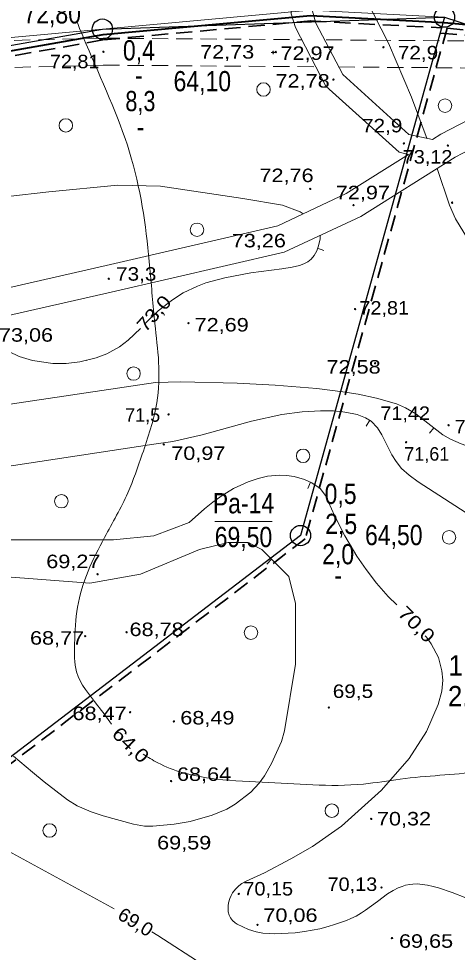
# Model space of a CAD drawing. Extents: x 628176 to 629009, y 6439913 to 6440496.
# Drawn here: x 628531.9 to 628597, y 6440288.3 to 6440426.6 of the extents above; entities that cross this region are included whole.
import ezdxf
from ezdxf.enums import TextEntityAlignment as Align

# ---------------------------------------------------------------- set-up
doc = ezdxf.new("R2010")
doc.units = 0
doc.header["$LTSCALE"] = 0.8
doc.linetypes.add('MEDIUM_DASHED', pattern=[4.5, 3, -1.5])
for name, color, linetype, lineweight in [('1', 7, 'Continuous', 13), ('11', 7, 'Continuous', 13), ('12', 7, 'Continuous', 13), ('14', 7, 'Continuous', 25), ('16', 7, 'Continuous', 13), ('21', 7, 'MEDIUM_DASHED', 35), ('3', 7, 'Continuous', 13)]:
    doc.layers.add(name, color=color, linetype=linetype, lineweight=lineweight)

msp = doc.modelspace()

# ---------------------------------------------------------------- hatches: boundary and pattern name
at = {"layer": '1'}
for points in [[(628544.6156, 6440421.7562, 1), (628544.4156, 6440421.7562, 1)], [(628569.7739, 6440421.6419, 1), (628569.5739, 6440421.6419, 1)], [(628570.1672, 6440421.7093, 1), (628569.9672, 6440421.7093, 1)], [(628586.1488, 6440422.4212, 1), (628585.9488, 6440422.4212, 1)], [(628578.7353, 6440417.613, 1), (628578.5353, 6440417.613, 1)], [(628589.1774, 6440408.173, 1), (628588.9774, 6440408.173, 1)], [(628595.7088, 6440407.8353, 1), (628595.5088, 6440407.8353, 1)], [(628575.2928, 6440401.4134, 1), (628575.0928, 6440401.4134, 1)], [(628596.329, 6440399.3821, 1), (628596.129, 6440399.3821, 1)], [(628581.7064, 6440399.0352, 1), (628581.5064, 6440399.0352, 1)], [(628570.9599, 6440394.0094, 1), (628570.7599, 6440394.0094, 1)], [(628545.4093, 6440388.101, 1), (628545.2093, 6440388.101, 1)], [(628581.9348, 6440383.6154, 1), (628581.7348, 6440383.6154, 1)], [(628557.2245, 6440381.5249, 1), (628557.0245, 6440381.5249, 1)], [(628584.9118, 6440375.5862, 1), (628584.7118, 6440375.5862, 1)], [(628554.2758, 6440368.0094, 1), (628554.0758, 6440368.0094, 1)], [(628595.8117, 6440366.4053, 1), (628595.6117, 6440366.4053, 1)], [(628553.5654, 6440363.5639, 1), (628553.3654, 6440363.5639, 1)], [(628589.5007, 6440363.8819, 1), (628589.3007, 6440363.8819, 1)], [(628543.7614, 6440344.3181, 1), (628543.5614, 6440344.3181, 1)], [(628548.0623, 6440335.7123, 1), (628547.8623, 6440335.7123, 1)], [(628541.9325, 6440335.1404, 1), (628541.7325, 6440335.1404, 1)], [(628578.0506, 6440324.5525, 1), (628577.8506, 6440324.5525, 1)], [(628548.5758, 6440323.8709, 1), (628548.3758, 6440323.8709, 1)], [(628555.0651, 6440322.5003, 1), (628554.8651, 6440322.5003, 1)], [(628554.6487, 6440313.6713, 1), (628554.4487, 6440313.6713, 1)], [(628584.3303, 6440308.048, 1), (628584.1303, 6440308.048, 1)], [(628560.1473, 6440304.6241, 1), (628559.9473, 6440304.6241, 1)], [(628564.6969, 6440296.9314, 1), (628564.4969, 6440296.9314, 1)], [(628585.8622, 6440297.8938, 1), (628585.6622, 6440297.8938, 1)], [(628567.4708, 6440292.3538, 1), (628567.2708, 6440292.3538, 1)], [(628587.4153, 6440290.3952, 1), (628587.2153, 6440290.3952, 1)]]:
    msp.add_hatch(color=256, dxfattribs=at).paths.add_polyline_path(points)

# ---------------------------------------------------------------- linework, layer by layer
for p, q in [((628576.01, 6440426), (628580, 6440418.38)), ((628573, 6440425.35), (628577.48, 6440416.66)), ((628569.67, 6440421.64), (628569.42, 6440421.64)), ((628569.67, 6440421.64), (628569.67, 6440421.89)), ((628569.67, 6440421.64), (628569.67, 6440421.39)), ((628569.67, 6440421.64), (628569.92, 6440421.64)), ((628580, 6440418.38), (628589.79, 6440409.49)), ((628577.48, 6440416.66), (628588.36, 6440406.85)), ((628605.41, 6440415.18), (628594.58, 6440409.55)), ((628607.25, 6440411.62), (628596.67, 6440406.14)), ((628589.79, 6440409.49), (628593.3, 6440408.74)), ((628594.58, 6440409.55), (628593.3, 6440408.74)), ((628589.76, 6440406.52), (628580.53, 6440400.72)), ((628588.36, 6440406.85), (628589.76, 6440406.52)), ((628596.67, 6440406.14), (628582.68, 6440397.35)), ((628580.53, 6440400.72), (628570.38, 6440395.95)), ((628582.68, 6440397.35), (628571.34, 6440392.07)), ((628570.38, 6440395.95), (628544.93, 6440390.06)), ((628571.34, 6440392.07), (628545.69, 6440386.14)), ((628544.93, 6440390.06), (628489.7, 6440377.44)), ((628545.69, 6440386.14), (628490.46, 6440373.52))]:
    msp.add_line(p, q, dxfattribs=at)
at = {"layer": '1', "linetype": 'MEDIUM_DASHED'}
for p, q in [((628544.47, 6440423.76), (628531.15, 6440423.43)), ((628544.53, 6440423.76), (628573.94, 6440423.53)), ((628577.55, 6440423.51), (628605.07, 6440423.3)), ((628544.56, 6440419.76), (628531.24, 6440419.43)), ((628544.5, 6440419.76), (628576.01, 6440419.52)), ((628579.42, 6440419.49), (628605.04, 6440419.3))]:
    msp.add_line(p, q, dxfattribs=at)
at = {"layer": '1'}
for points in [[(628576.01, 6440426), (628575.38, 6440428.31), (628576, 6440430.63), (628579.19, 6440436.17), (628580.37, 6440438.23)], [(628572.35, 6440429), (628572.35, 6440427.37), (628573, 6440425.35)]]:
    msp.add_lwpolyline(points, dxfattribs=at)
for centre, radius in [((628544.5156, 6440421.7562), 0.1), ((628569.6739, 6440421.6419), 0.1), ((628570.0672, 6440421.7093), 0.1), ((628586.0488, 6440422.4212), 0.1), ((628578.6353, 6440417.613), 0.1), ((628568.2597, 6440416.1603), 1), ((628595.1825, 6440413.7612), 1), ((628538.9379, 6440410.829), 1), ((628589.0774, 6440408.173), 0.1), ((628595.6088, 6440407.8353), 0.1), ((628575.1928, 6440401.4134), 0.1), ((628596.229, 6440399.3821), 0.1), ((628581.6064, 6440399.0352), 0.1), ((628558.3969, 6440395.3684), 1), ((628570.8599, 6440394.0094), 0.1), ((628545.3093, 6440388.101), 0.1), ((628581.8348, 6440383.6154), 0.1), ((628557.1245, 6440381.5249), 0.1), ((628548.9908, 6440374.0544), 1), ((628584.8118, 6440375.5862), 0.1), ((628554.1758, 6440368.0094), 0.1), ((628595.7117, 6440366.4053), 0.1), ((628553.4654, 6440363.5639), 0.1), ((628589.4007, 6440363.8819), 0.1), ((628574.1317, 6440361.8574), 1), ((628538.2873, 6440355.1365), 1), ((628595.7826, 6440349.7863), 1), ((628543.6614, 6440344.3181), 0.1), ((628547.9623, 6440335.7123), 0.1), ((628566.3938, 6440335.6585), 1), ((628541.8325, 6440335.1404), 0.1), ((628577.9506, 6440324.5525), 0.1), ((628548.4758, 6440323.8709), 0.1), ((628554.9651, 6440322.5003), 0.1), ((628554.5487, 6440313.6713), 0.1), ((628578.3891, 6440309.2689), 1), ((628584.2303, 6440308.048), 0.1), ((628536.5388, 6440306.3367), 1), ((628560.0473, 6440304.6241), 0.1), ((628564.5969, 6440296.9314), 0.1), ((628585.7622, 6440297.8938), 0.1), ((628567.3708, 6440292.3538), 0.1), ((628587.3153, 6440290.3952), 0.1)]:
    msp.add_circle(centre, radius, dxfattribs=at)
at = {"layer": '11'}
for points in [[(628393.19, 6440398.39), (628410.48, 6440417.82), (628464.14, 6440417.8), (628544.36, 6440425.1), (628575.19, 6440427.91), (628595.11, 6440426.87)], [(628595.11, 6440426.87), (628573.75, 6440350.05), (628485.59, 6440282.78), (628547.63, 6440210.77)], [(628393.19, 6440398.39), (628479.31, 6440413.61), (628544.36, 6440425.1)]]:
    msp.add_lwpolyline(points, dxfattribs=at)
at = {"layer": '12'}
msp.add_line((628561.03, 6440352.12), (628569.52, 6440352.12), dxfattribs=at)
at = {"layer": '12', "lineweight": 25}
for centre in [(628595.106, 6440426.8687), (628544.3614, 6440425.1034), (628573.7492, 6440350.0463)]:
    msp.add_circle(centre, 1.5, dxfattribs=at)
at = {"layer": '14'}
for points in [[(628595.11, 6440426.87), (628573.75, 6440350.05), (628485.59, 6440282.78)], [(628544.36, 6440425.1), (628595.11, 6440426.87), (628648, 6440409.69), (628709.76, 6440416.52)], [(628393.19, 6440398.39), (628479.31, 6440413.61), (628544.36, 6440425.1)]]:
    msp.add_lwpolyline(points, dxfattribs=at)
at = {"layer": '16'}
for points in [[(628540.53, 6440426.33), (628542.39, 6440421.88), (628548.7, 6440405.83), (628551.42, 6440389.63), (628552.14, 6440381.46), (628552.71, 6440375.73), (628552.43, 6440369.71), (628550.28, 6440362.11), (628548.13, 6440356.38), (628544.69, 6440349.78), (628542.25, 6440344.77), (628540.67, 6440339.46), (628540.24, 6440334.02), (628540.53, 6440329.86), (628543.68, 6440324.84), (628545.7, 6440322.12)], [(628550.39, 6440317.66), (628552.57, 6440316.38), (628560.31, 6440314.09), (628568.05, 6440313.52), (628583.1, 6440313.23), (628588.55, 6440313.95), (628594.43, 6440314.52), (628600.16, 6440315.09), (628607.18, 6440315.95), (628615.21, 6440313.23), (628618.36, 6440310.51), (628620.37, 6440309.07)]]:
    msp.add_spline(points, degree=3, dxfattribs=at)
at = {"layer": '21'}
for p, q in [((628544.54, 6440423.51), (628575.28, 6440426.31)), ((628575.16, 6440426.31), (628594.66, 6440425.29)), ((628594.53, 6440424.51), (628704.5, 6440414.58)), ((628595.48, 6440425.23), (628706.25, 6440415.23)), ((628478.27, 6440411.8), (628544.61, 6440423.52))]:
    msp.add_line(p, q, dxfattribs=at)
at = {"layer": '21', "linetype": 'Continuous', "lineweight": 40}
for points in [[(628544.47, 6440424.31), (628575.21, 6440427.11), (628595.05, 6440426.07), (628708.01, 6440415.87)], [(628393.6, 6440397.65), (628479.44, 6440412.82), (628544.47, 6440424.31)]]:
    msp.add_lwpolyline(points, dxfattribs=at)
at = {"layer": '21'}
msp.add_lwpolyline([(628595.48, 6440425.23), (628574.45, 6440349.57), (628486.75, 6440282.66), (628547.03, 6440212.69)], dxfattribs=at)
at = {"layer": '3'}
for p, q in [((628586.79, 6440423), (628583.48, 6440429.52)), ((628592.48, 6440408.92), (628592.11, 6440410)), ((628595.86, 6440399), (628594, 6440404.46)), ((628565.2, 6440400), (628571.1, 6440399)), ((628577.23, 6440392.31), (628576.29, 6440392.65)), ((628571, 6440389.6), (628572.5, 6440389.84)), ((628572.5, 6440389.84), (628573.59, 6440390.08)), ((628573.59, 6440390.08), (628574.26, 6440390.31)), ((628556.35, 6440386), (628558.49, 6440387)), ((628558.49, 6440387), (628559.72, 6440387.49)), ((628548.21, 6440379), (628550, 6440380.72)), ((628546.88, 6440378), (628548.21, 6440379)), ((628542, 6440376), (628542.08, 6440376.04)), ((628588, 6440369.55), (628589.3, 6440369)), ((628571, 6440368), (628574, 6440368.39)), ((628574, 6440368.39), (628576.69, 6440368.55)), ((628576.69, 6440368.55), (628578.63, 6440368.52)), ((628578.63, 6440368.52), (628580, 6440368.4)), ((628580, 6440368.4), (628581.43, 6440368.16)), ((628583.49, 6440366.28), (628584.01, 6440367.13)), ((628592.9, 6440365.21), (628593.52, 6440366)), ((628514, 6440357.84), (628552, 6440363.59)), ((628572.79, 6440358.8), (628571.68, 6440358.96)), ((628574.34, 6440358.35), (628572.79, 6440358.8)), ((628574.81, 6440357.03), (628575.23, 6440357.94)), ((628568.76, 6440345.83), (628569.47, 6440346.53)), ((628521.72, 6440344.58), (628542.5, 6440343)), ((628586.76, 6440341), (628588.01, 6440339.77)), ((628592.24, 6440335.2), (628592.41, 6440335)), ((628569.43, 6440316.25), (628568.4, 6440314.46)), ((628589.87, 6440317), (628585.76, 6440312.3)), ((628585.76, 6440312.3), (628579.83, 6440307)), ((628562.81, 6440309.49), (628560.65, 6440308.62)), ((628564.06, 6440310.24), (628562.81, 6440309.49)), ((628544.46, 6440308.51), (628542.7, 6440309.1)), ((628560.65, 6440308.62), (628557.38, 6440307.68)), ((628551.83, 6440307), (628550.6, 6440307)), ((628575.54, 6440303.99), (628579.83, 6440307)), ((628575.54, 6440303.99), (628572.31, 6440302.14)), ((628589.95, 6440298.34), (628590.39, 6440298.39)), ((628592.59, 6440298.22), (628591.77, 6440298.36)), ((628586.67, 6440296.93), (628585.18, 6440295.81)), ((628593.44, 6440298.03), (628592.59, 6440298.22)), ((628563.09, 6440295.64), (628563.02, 6440295.16)), ((628563.25, 6440296.25), (628563.09, 6440295.64)), ((628585.18, 6440295.81), (628583.4, 6440294.54)), ((628545.67, 6440295), (628546.11, 6440294.73)), ((628563.02, 6440295.16), (628563, 6440294.7)), ((628582.79, 6440294.13), (628581.98, 6440293.66)), ((628582.79, 6440294.13), (628583.4, 6440294.54)), ((628580.57, 6440293.02), (628578.8, 6440292.41)), ((628581.22, 6440293.3), (628580.57, 6440293.02)), ((628581.22, 6440293.3), (628581.98, 6440293.66)), ((628564.05, 6440292.64), (628564.34, 6440292.44)), ((628576.61, 6440291.79), (628577.83, 6440292.12)), ((628577.83, 6440292.12), (628578.8, 6440292.41)), ((628551.7, 6440291.31), (628552.58, 6440290.77)), ((628568.18, 6440291.14), (628569.16, 6440291.06))]:
    msp.add_line(p, q, dxfattribs=at)
for points in [[(628586.79, 6440423), (628590.19, 6440415), (628592.11, 6440410)], [(628546.67, 6440402), (628536.41, 6440401), (628530.34, 6440400.3)], [(628546.67, 6440402), (628553, 6440401.85), (628565.2, 6440400)], [(628574.15, 6440397.72), (628573.7, 6440398), (628571.1, 6440399)], [(628595.86, 6440399), (628596.71, 6440397), (628601, 6440390), (628602.46, 6440388.25)], [(628574.26, 6440390.31), (628574.81, 6440390.62), (628575.32, 6440391), (628575.76, 6440391.54), (628576.15, 6440392.25), (628576.41, 6440393), (628576.66, 6440394), (628576.66, 6440394.55)], [(628559.72, 6440387.49), (628562.53, 6440388.24), (628566.38, 6440389), (628571, 6440389.6)], [(628550.65, 6440381.45), (628552.63, 6440383.34), (628554.75, 6440385), (628556.35, 6440386)], [(628524.67, 6440381.33), (628526, 6440380), (628529, 6440378), (628532, 6440376.58), (628534, 6440376), (628537, 6440375.54), (628539, 6440375.54), (628541, 6440375.77), (628543.42, 6440376.37), (628545.01, 6440377), (628546.88, 6440378)], [(628489.46, 6440373.3), (628493.55, 6440372), (628497.15, 6440371), (628501.63, 6440370), (628507.31, 6440369), (628511.97, 6440368.43), (628516, 6440368.36), (628521.67, 6440368.48), (628526, 6440368.81), (628552.26, 6440372.74), (628556, 6440372.85), (628564.33, 6440372.65), (628570, 6440372.36), (628576.16, 6440371.82), (628580, 6440371.37), (628582.3, 6440371), (628585, 6440370.41), (628588, 6440369.55)], [(628589.3, 6440369), (628590.86, 6440368.09), (628593.52, 6440366)], [(628571, 6440368), (628566.48, 6440367), (628562.9, 6440366), (628559.18, 6440365), (628554.79, 6440364), (628552, 6440363.59)], [(628599, 6440352.99), (628591.21, 6440358), (628589.84, 6440359), (628588.72, 6440360), (628587.91, 6440361), (628587.28, 6440362), (628586.81, 6440363), (628585.8, 6440365), (628585.15, 6440366), (628584.23, 6440367), (628583.37, 6440367.52), (628582.13, 6440368), (628581.43, 6440368.16)], [(628593.52, 6440366), (628594.87, 6440365), (628596, 6440364.31), (628597.58, 6440363.65), (628600.58, 6440362.58), (628602.79, 6440362), (628605, 6440361.65), (628607, 6440361.52), (628608, 6440361.54), (628612.98, 6440362)], [(628557.22, 6440352), (628559.49, 6440354), (628560.72, 6440355), (628562.15, 6440356), (628563.83, 6440357), (628566, 6440358), (628567.45, 6440358.51), (628568.87, 6440358.83), (628570.56, 6440359.01), (628571.68, 6440358.96)], [(628574.34, 6440358.35), (628575.44, 6440357.84), (628576.67, 6440357), (628577.43, 6440356), (628578.77, 6440353), (628580.33, 6440350), (628582.1, 6440347), (628583.49, 6440345), (628585.02, 6440343), (628586.76, 6440341)], [(628524, 6440349.41), (628546, 6440349.41), (628552, 6440350), (628557.22, 6440352)], [(628558.76, 6440348), (628563, 6440349), (628566, 6440349), (628568, 6440348)], [(628542.5, 6440343), (628550, 6440344.32), (628558.76, 6440348)], [(628568, 6440348), (628572, 6440344), (628573, 6440340), (628573, 6440331), (628571.35, 6440321.1)], [(628592.41, 6440335), (628593.14, 6440334), (628594.21, 6440332), (628594.72, 6440330), (628594.84, 6440328.64), (628594.71, 6440327), (628594.17, 6440325), (628592.45, 6440321), (628589.87, 6440317)], [(628571.35, 6440321.1), (628570.91, 6440319.54), (628569.43, 6440316.25)], [(628535.74, 6440313.55), (628534, 6440315), (628531.18, 6440317.35)], [(628542.7, 6440309.1), (628540.6, 6440310), (628539.17, 6440310.88), (628535.74, 6440313.55)], [(628568.4, 6440314.46), (628567.62, 6440313.37), (628566.36, 6440312), (628564.06, 6440310.24)], [(628511, 6440313), (628520, 6440309), (628531, 6440303), (628545.67, 6440295)], [(628550.6, 6440307), (628549, 6440307.26), (628544.46, 6440308.51)], [(628557.38, 6440307.68), (628555, 6440307.29), (628551.83, 6440307)], [(628563.25, 6440296.25), (628563.45, 6440296.73), (628563.68, 6440297.12), (628564.09, 6440297.63), (628564.6, 6440298.14), (628565.07, 6440298.48), (628565.69, 6440298.82), (628568.39, 6440300.09), (628572.31, 6440302.14)], [(628589.95, 6440298.34), (628589.31, 6440298.22), (628588.81, 6440298.06), (628588.21, 6440297.82), (628587.49, 6440297.46), (628586.67, 6440296.93)], [(628591.77, 6440298.36), (628591.08, 6440298.42), (628590.39, 6440298.39)], [(628611.1, 6440289), (628608.85, 6440291), (628605.61, 6440293), (628601.59, 6440295.01), (628598.29, 6440296.37), (628596.23, 6440297.14), (628594.2, 6440297.83), (628593.44, 6440298.03)], [(628564.05, 6440292.64), (628563.67, 6440293), (628563.37, 6440293.42), (628563.19, 6440293.8), (628563.04, 6440294.3), (628563, 6440294.7)], [(628568.18, 6440291.14), (628567.19, 6440291.3), (628566.02, 6440291.66), (628564.34, 6440292.44)], [(628576.61, 6440291.79), (628574.33, 6440291.35), (628572.95, 6440291.16), (628569.85, 6440291.05), (628569.16, 6440291.06)], [(628552.58, 6440290.77), (628559.18, 6440286.53), (628571.81, 6440278.47), (628576.1, 6440275.19)]]:
    msp.add_lwpolyline(points, dxfattribs=at)

# ---------------------------------------------------------------- texts
at = {"layer": '1'}
for s, width, p in [('72,73', 1.2, (628558.85, 6440420.73)), ('72,97', 1.2, (628570.77, 6440420.54)), ('72,9', 1.15, (628588.18, 6440420.62)), ('72,81', 1.1, (628536.57, 6440419.3)), ('72,78', 1.2, (628570.04, 6440416.43)), ('72,9', 1.15, (628582.87, 6440409.8)), ('73,12', 1.1, (628588.91, 6440405.18)), ('72,76', 1.2, (628567.66, 6440402.43)), ('72,97', 1.2, (628578.98, 6440399.89)), ('73,26', 1.2, (628563.55, 6440392.76)), ('73,3', 1.15, (628546.39, 6440387.82)), ('72,81', 1.1, (628582.48, 6440382.79)), ('72,69', 1.2, (628558.04, 6440380.29)), ('73,06', 1.2, (628529.02, 6440378.78)), ('72,58', 1.2, (628577.6, 6440374.05)), ('71,42', 1.1, (628585.59, 6440367.18)), ('72,13', 1.1, (628596.6, 6440365.19)), ('70,97', 1.2, (628554.58, 6440361.26)), ('69,27', 1.2, (628536.04, 6440345.22)), ('68,78', 1.2, (628548.39, 6440335.15)), ('68,77', 1.2, (628533.63, 6440333.88)), ('69,5', 1.15, (628578.53, 6440325.98)), ('68,47', 1.2, (628539.93, 6440322.7)), ('68,49', 1.2, (628555.92, 6440322.05)), ('68,64', 1.2, (628555.43, 6440313.69)), ('70,32', 1.2, (628585.08, 6440307.09)), ('69,59', 1.2, (628552.48, 6440303.54)), ('70,15', 1.1, (628565.28, 6440296.71)), ('70,13', 1.1, (628577.76, 6440297.38)), ('70,06', 1.2, (628568.24, 6440292.79)), ('69,65', 1.2, (628588.35, 6440288.96))]:
    msp.add_text(s, height=2, dxfattribs=dict(at, width=width)).set_placement(p)
for s, p in [('71,5', (628547.73, 6440366.91)), ('71,61', (628589.13, 6440361.15))]:
    msp.add_text(s, height=2, dxfattribs=at).set_placement(p)
at = {"layer": '12'}
for s, width, p in [('72,80', 0.85, (628536.925, 6440425.94)), ('0,4', 0.85, (628549.78, 6440420.46)), ('64,10', 0.85, (628559.185, 6440415.89)), ('-', 0.85, (628549.78, 6440416.78)), ('8,3', 0.8, (628550.005, 6440412.94)), ('-', 0.85, (628550.03, 6440409.13)), ('0,5', 0.85, (628579.69, 6440354.73)), ('Pa-14', 0.85, (628565.295, 6440353.34)), ('2,5', 0.85, (628579.78, 6440350.28)), ('69,50', 0.85, (628565.29, 6440348.34)), ('64,50', 0.85, (628587.585, 6440348.63)), ('2,0', 0.85, (628579.33, 6440345.79)), ('-', 0.85, (628579.35, 6440342.67))]:
    msp.add_text(s, height=3, dxfattribs=dict(at, width=width)).set_placement(p, align=Align.CENTER)
at = {"layer": '16', "width": 1.2}
msp.add_text('64,0', height=2, rotation=316.236, dxfattribs=at).set_placement((628547.8783, 6440318.3105), align=Align.CENTER)
at = {"layer": '21', "width": 0.95}
for s, p in [('1. PLOKK', (628604.165, 6440329.31)), ('2. PLOKK', (628604.095, 6440324.76))]:
    msp.add_text(s, height=3, dxfattribs=at).set_placement(p, align=Align.CENTER)
at = {"layer": '3'}
for s, rotation, width, p in [('73,0', 48.234, 1.15, (628550.77, 6440380.08)), ('70,0', 315.559, 1.2, (628588.03, 6440338.36)), ('69,0', 328.535, 1.05, (628546.45, 6440293.35))]:
    msp.add_text(s, height=2, rotation=rotation, dxfattribs=dict(at, width=width)).set_placement(p)

doc.saveas('drawing.dxf')
